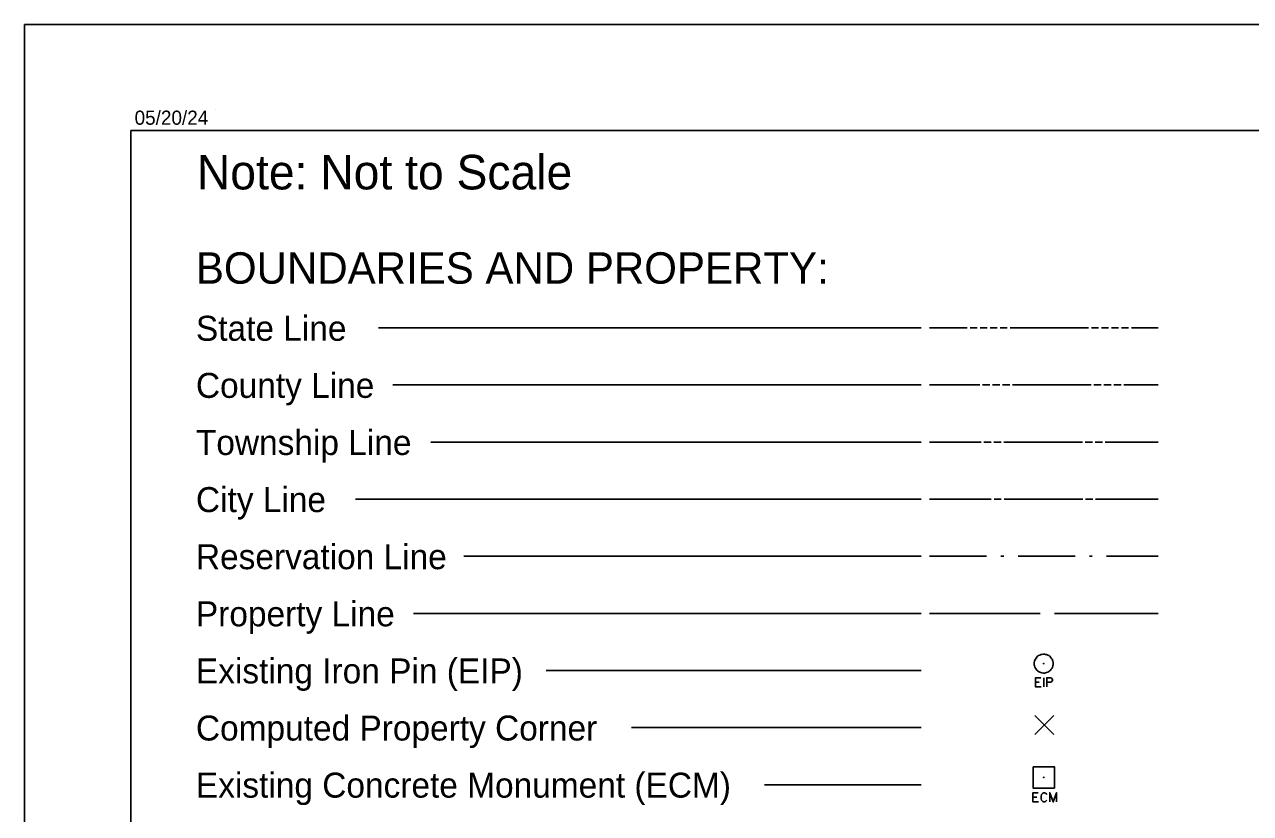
# Model space of a CAD drawing. Extents: x 2040834 to 2047174, y 618431 to 621625.
# Drawn here: x 2045074 to 2045579, y 621299 to 621625 of the extents above; entities that cross this region are included whole.
import ezdxf

# ---------------------------------------------------------------- set-up
doc = ezdxf.new("R2010")
doc.units = 0
doc.layers.add('Default', color=7, linetype='Continuous')

msp = doc.modelspace()

# ---------------------------------------------------------------- linework, layer by layer
at = {"layer": 'Default'}
for p, q in [((2047057.71, 621624.54), (2045074.38, 621624.54)), ((2045074.38, 621624.54), (2045074.38, 620341.21)), ((2045153.08, 621589.58), (2045153.08, 621589.58)), ((2045118.13, 620384.96), (2045118.13, 621580.79)), ((2047013.96, 621580.79), (2045118.13, 621580.79)), ((2045443.84, 621499.51), (2045220.21, 621499.51)), ((2045447.22, 621499.51), (2045462.76, 621499.51)), ((2045463.94, 621499.51), (2045466.88, 621499.51)), ((2045468.06, 621499.51), (2045471, 621499.51)), ((2045472.18, 621499.51), (2045475.12, 621499.51)), ((2045476.3, 621499.51), (2045479.24, 621499.51)), ((2045480.42, 621499.51), (2045512.79, 621499.51)), ((2045513.96, 621499.51), (2045516.91, 621499.51)), ((2045518.08, 621499.51), (2045521.03, 621499.51)), ((2045522.2, 621499.51), (2045525.15, 621499.51)), ((2045526.32, 621499.51), (2045529.27, 621499.51)), ((2045530.44, 621499.51), (2045541.39, 621499.51)), ((2045443.84, 621475.97), (2045226.08, 621475.97)), ((2045447.22, 621475.97), (2045467.92, 621475.97)), ((2045469.1, 621475.97), (2045472.04, 621475.97)), ((2045473.22, 621475.97), (2045476.16, 621475.97)), ((2045477.34, 621475.97), (2045480.28, 621475.97)), ((2045481.46, 621475.97), (2045513.83, 621475.97)), ((2045515.01, 621475.97), (2045517.95, 621475.97)), ((2045519.13, 621475.97), (2045522.07, 621475.97)), ((2045523.25, 621475.97), (2045526.19, 621475.97)), ((2045527.37, 621475.97), (2045541.39, 621475.97)), ((2045443.84, 621452.43), (2045241.73, 621452.43)), ((2045447.22, 621452.43), (2045468.47, 621452.43)), ((2045469.65, 621452.43), (2045472.59, 621452.43)), ((2045473.77, 621452.43), (2045476.71, 621452.43)), ((2045477.89, 621452.43), (2045510.26, 621452.43)), ((2045511.43, 621452.43), (2045514.38, 621452.43)), ((2045515.55, 621452.43), (2045518.5, 621452.43)), ((2045519.67, 621452.43), (2045541.39, 621452.43)), ((2045443.84, 621428.89), (2045210.69, 621428.89)), ((2045447.22, 621428.89), (2045472.69, 621428.89)), ((2045473.87, 621428.89), (2045476.81, 621428.89)), ((2045477.99, 621428.89), (2045510.36, 621428.89)), ((2045511.54, 621428.89), (2045514.48, 621428.89)), ((2045515.66, 621428.89), (2045541.39, 621428.89)), ((2045443.84, 621405.35), (2045255.42, 621405.35)), ((2045447.22, 621405.35), (2045470.76, 621405.35)), ((2045476.65, 621405.35), (2045477.83, 621405.35)), ((2045483.71, 621405.35), (2045507.25, 621405.35)), ((2045513.14, 621405.35), (2045514.32, 621405.35)), ((2045520.2, 621405.35), (2045541.39, 621405.35)), ((2045443.84, 621381.8), (2045234.71, 621381.8)), ((2045447.22, 621381.8), (2045492.84, 621381.8)), ((2045498.72, 621381.8), (2045541.39, 621381.8)), ((2045443.84, 621358.26), (2045289.3, 621358.26)), ((2045494.32, 621351.49), (2045494.32, 621355.26)), ((2045490.94, 621353.39), (2045492.48, 621353.39)), ((2045498.44, 621331.87), (2045490.66, 621339.65)), ((2045490.66, 621331.87), (2045498.44, 621339.65)), ((2045443.84, 621334.72), (2045324.43, 621334.72)), ((2045443.84, 621311.18), (2045379.3, 621311.18)), ((2045489.86, 621306), (2045491.41, 621306))]:
    msp.add_line(p, q, dxfattribs=at)
for points in [[(2045498.19, 621361.09), (2045498.15, 621361.59), (2045498.06, 621362.06), (2045497.9, 621362.53), (2045497.72, 621362.96), (2045497.43, 621363.37), (2045497.12, 621363.75), (2045496.78, 621364.09), (2045496.37, 621364.37), (2045495.97, 621364.62), (2045495.5, 621364.78), (2045495.03, 621364.9), (2045494.56, 621364.97), (2045494.06, 621364.97), (2045493.56, 621364.9), (2045493.09, 621364.78), (2045492.65, 621364.62), (2045492.21, 621364.37), (2045491.8, 621364.09), (2045491.46, 621363.75), (2045491.15, 621363.37), (2045490.9, 621362.96), (2045490.68, 621362.53), (2045490.52, 621362.06), (2045490.43, 621361.59), (2045490.4, 621361.09), (2045490.43, 621360.59), (2045490.52, 621360.12), (2045490.68, 621359.65), (2045490.9, 621359.21), (2045491.15, 621358.8), (2045491.46, 621358.43), (2045491.8, 621358.08), (2045492.21, 621357.8), (2045492.65, 621357.55), (2045493.09, 621357.4), (2045493.56, 621357.27), (2045494.06, 621357.21), (2045494.56, 621357.21), (2045495.03, 621357.27), (2045495.5, 621357.4), (2045495.97, 621357.55), (2045496.37, 621357.8), (2045496.78, 621358.08), (2045497.12, 621358.43), (2045497.43, 621358.8), (2045497.72, 621359.21), (2045497.9, 621359.65), (2045498.06, 621360.12), (2045498.15, 621360.59), (2045498.19, 621361.09)], [(2045494.37, 621361.18), (2045494.28, 621361.21), (2045494.21, 621361.15), (2045494.18, 621361.06), (2045494.24, 621360.99), (2045494.34, 621360.96), (2045494.4, 621361.03), (2045494.43, 621361.12), (2045494.37, 621361.18)], [(2045493.1, 621355.26), (2045490.94, 621355.26), (2045490.94, 621351.49), (2045493.25, 621351.49)], [(2045495.56, 621351.49), (2045495.56, 621355.26), (2045497.08, 621355.26), (2045497.52, 621355.11), (2045497.91, 621354.52), (2045497.91, 621354.16), (2045497.55, 621353.57), (2045497.08, 621353.42), (2045495.56, 621353.42)], [(2045489.89, 621318.58), (2045498.71, 621318.58), (2045498.71, 621309.76), (2045489.89, 621309.76), (2045489.89, 621318.58)], [(2045494.28, 621314.28), (2045494.23, 621314.24), (2045494.23, 621314.15), (2045494.32, 621314.06), (2045494.41, 621314.11), (2045494.45, 621314.2), (2045494.36, 621314.28), (2045494.28, 621314.28)], [(2045492.03, 621307.87), (2045489.86, 621307.87), (2045489.86, 621304.1), (2045492.18, 621304.1)], [(2045495.59, 621307.13), (2045495.11, 621307.75), (2045494.64, 621307.87), (2045494.31, 621307.87), (2045493.87, 621307.75), (2045493.36, 621307.13), (2045493.24, 621306.3), (2045493.24, 621305.85), (2045493.24, 621305.56), (2045493.27, 621305.29), (2045493.36, 621304.81), (2045493.87, 621304.22), (2045494.31, 621304.1), (2045494.58, 621304.1), (2045495.08, 621304.22), (2045495.59, 621304.81)], [(2045496.8, 621304.1), (2045496.8, 621307.87), (2045498.23, 621304.1), (2045499.59, 621307.87), (2045499.59, 621304.1)]]:
    msp.add_lwpolyline(points, dxfattribs=at)

# ---------------------------------------------------------------- texts
for s, height, rotation, p in [('05/20/24', 5.833, 0, (2045119.73, 621583.21)), ('Note: Not to Scale', 14.2517, 360, (2045145.39, 621556.56))]:
    msp.add_text(s, height=height, rotation=rotation, dxfattribs=at).set_placement(p)
for s, height, p in [('BOUNDARIES AND PROPERTY:', 12.9481, (2045144.99, 621517.7)), ('State Line', 10.3, (2045145, 621494.17)), ('County Line', 10.2996, (2045145, 621470.63)), ('Township Line', 10.2996, (2045145, 621447.09)), ('City Line', 10.3, (2045145, 621423.55)), ('Reservation Line', 10.2996, (2045145, 621400.01)), ('Property Line', 10.2996, (2045145, 621376.46)), ('Existing Iron Pin (EIP)', 10.2996, (2045145, 621352.92)), ('Computed Property Corner', 10.2996, (2045145, 621329.38)), ('Existing Concrete Monument (ECM)', 10.2996, (2045145, 621305.84))]:
    msp.add_text(s, height=height, dxfattribs=at).set_placement(p)

doc.saveas('drawing.dxf')
